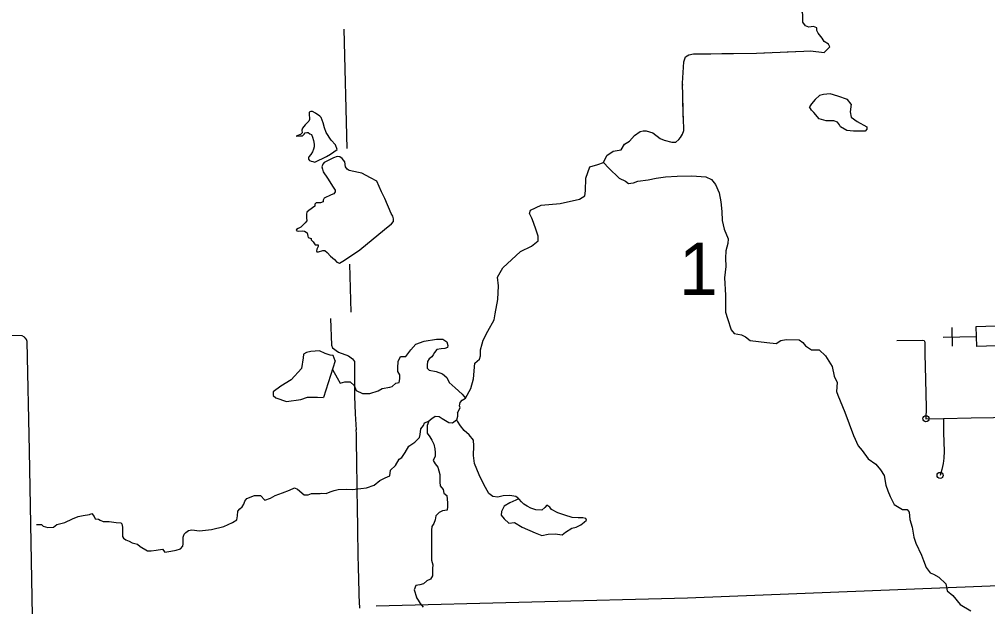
# Model space of a CAD drawing. Extents: x 1367863 to 1368197, y 380048 to 380261.
# Drawn here: x 1368042.42 to 1368072.73, y 380146.25 to 380164.65 of the extents above; entities that cross this region are included whole.
import ezdxf

# ---------------------------------------------------------------- set-up
doc = ezdxf.new("R2010")
doc.units = 0
for name, color, linetype in [('Level 31', 7, 'Continuous'), ('Level 32', 7, 'Continuous'), ('Level 35', 7, 'Continuous'), ('Level 43', 7, 'Continuous'), ('Level 5', 7, 'Continuous'), ('Level 57', 7, 'Continuous')]:
    doc.layers.add(name, color=color, linetype=linetype)

msp = doc.modelspace()

# ---------------------------------------------------------------- linework, layer by layer
at = {"layer": 'Level 31'}
for points in [[(1368069.889, 380154.586), (1368070.694, 380154.598), (1368070.74, 380154.586), (1368070.751, 380154.563), (1368070.763, 380154.511), (1368070.769, 380154.169), (1368070.786, 380153.37), (1368070.803, 380152.478), (1368070.798, 380152.136)], [(1368071.348, 380152.148), (1368072.216, 380152.165), (1368072.916, 380152.177), (1368073.512, 380152.189)], [(1368070.798, 380152.136), (1368071.348, 380152.148)], [(1368071.348, 380152.148), (1368071.353, 380151.691), (1368071.371, 380151.123), (1368071.359, 380150.897), (1368071.342, 380150.729), (1368071.301, 380150.55), (1368071.243, 380150.359)], [(1368053, 380149.528), (1368052.997, 380149.725), (1368052.995, 380149.921), (1368052.992, 380150.113), (1368052.989, 380150.303), (1368052.986, 380150.49), (1368052.984, 380150.676), (1368052.981, 380150.856), (1368052.978, 380151.026), (1368052.973, 380151.181), (1368052.97, 380151.307), (1368052.97, 380151.413), (1368052.969, 380151.502), (1368052.969, 380151.58), (1368052.969, 380151.648), (1368052.967, 380151.708), (1368052.964, 380151.75), (1368052.963, 380151.784), (1368052.961, 380151.792)], [(1368053.078, 380146.203), (1368053.068, 380146.401), (1368053.06, 380146.599), (1368053.054, 380146.798), (1368053.05, 380146.996), (1368053.044, 380147.193), (1368053.037, 380147.387), (1368053.03, 380147.58), (1368053.025, 380147.773), (1368053.022, 380147.966), (1368053.02, 380148.161), (1368053.018, 380148.356), (1368053.017, 380148.551), (1368053.015, 380148.746), (1368053.011, 380148.94), (1368053.007, 380149.135), (1368053.004, 380149.331), (1368053, 380149.528)]]:
    msp.add_lwpolyline(points, dxfattribs=at)
for centre in [(1368070.798, 380152.136), (1368071.243, 380150.359)]:
    msp.add_circle(centre, 0.097, dxfattribs=at)
at = {"layer": 'Level 32'}
for points in [[(1368052.157, 380155.277), (1368052.189, 380154.437), (1368052.222, 380154.361), (1368052.407, 380154.219), (1368052.723, 380154.11), (1368052.843, 380154.012), (1368052.909, 380153.925), (1368052.909, 380153.75), (1368052.909, 380153.26), (1368052.909, 380152.846), (1368052.931, 380152.29), (1368052.961, 380151.792)], [(1368043.011, 380136.212), (1368042.731, 380151.129), (1368042.659, 380154.556), (1368042.643, 380154.618), (1368042.607, 380154.662), (1368042.594, 380154.674), (1368042.578, 380154.694), (1368042.51, 380154.734), (1368041.154, 380154.752)]]:
    msp.add_lwpolyline(points, dxfattribs=at)
at = {"layer": 'Level 35'}
for points in [[(1368067.608, 380163.609), (1368067.786, 380163.788), (1368067.748, 380163.873), (1368067.615, 380163.958), (1368067.546, 380164.06), (1368067.421, 380164.215), (1368067.382, 380164.293), (1368067.382, 380164.378), (1368067.274, 380164.428), (1368067.134, 380164.405), (1368067.033, 380164.443), (1368066.94, 380164.56), (1368066.94, 380164.599), (1368066.947, 380164.677), (1368066.947, 380164.785), (1368066.932, 380164.863), (1368066.87, 380164.948), (1368066.846, 380164.987), (1368066.839, 380165.034), (1368066.753, 380165.151), (1368066.536, 380165.492)], [(1368068.462, 380161.992), (1368068.338, 380162.132), (1368068.043, 380162.241), (1368067.802, 380162.311), (1368067.592, 380162.295), (1368067.468, 380162.257), (1368067.328, 380162.14), (1368067.212, 380162), (1368067.157, 380161.907)], [(1368068.462, 380161.992), (1368068.431, 380161.752), (1368068.462, 380161.588), (1368068.649, 380161.448), (1368068.952, 380161.285), (1368068.952, 380161.208), (1368068.897, 380161.145), (1368068.781, 380161.145), (1368068.532, 380161.145), (1368068.322, 380161.161), (1368068.128, 380161.285), (1368068.089, 380161.347), (1368068.035, 380161.425), (1368067.911, 380161.472), (1368067.678, 380161.464), (1368067.452, 380161.534), (1368067.289, 380161.728), (1368067.212, 380161.806), (1368067.157, 380161.907)], [(1368052.367, 380160.575), (1368052.315, 380160.713), (1368052.183, 380160.865), (1368052.019, 380161.101), (1368051.968, 380161.251), (1368051.93, 380161.406), (1368051.867, 380161.57), (1368051.827, 380161.613), (1368051.686, 380161.705), (1368051.597, 380161.759), (1368051.574, 380161.762), (1368051.539, 380161.762), (1368051.516, 380161.754), (1368051.488, 380161.734), (1368051.488, 380161.702), (1368051.488, 380161.659), (1368051.505, 380161.555), (1368051.505, 380161.506), (1368051.476, 380161.455), (1368051.37, 380161.34), (1368051.281, 380161.236), (1368051.264, 380161.179), (1368051.266, 380161.095), (1368051.215, 380161.041), (1368051.082, 380160.989), (1368051.206, 380160.998), (1368051.278, 380161.003), (1368051.332, 380161.046), (1368051.367, 380161.09), (1368051.422, 380161.098), (1368051.459, 380161.098), (1368051.511, 380161.061), (1368051.56, 380161.035), (1368051.591, 380160.957), (1368051.631, 380160.854), (1368051.643, 380160.733), (1368051.646, 380160.65), (1368051.628, 380160.581), (1368051.594, 380160.5), (1368051.545, 380160.414), (1368051.479, 380160.339), (1368051.465, 380160.305), (1368051.468, 380160.262), (1368051.496, 380160.224), (1368051.548, 380160.204), (1368051.603, 380160.198), (1368051.672, 380160.178)], [(1368056.138, 380152.323), (1368056.222, 380152.473), (1368056.199, 380152.535), (1368056.222, 380152.644), (1368056.284, 380152.714), (1368056.385, 380152.784), (1368056.548, 380153.087), (1368056.634, 380153.39), (1368056.681, 380153.88), (1368056.82, 380154.004), (1368056.851, 380154.105), (1368056.851, 380154.175), (1368056.851, 380154.299), (1368056.906, 380154.478), (1368056.937, 380154.602), (1368057.084, 380154.874), (1368057.286, 380155.232), (1368057.317, 380155.418), (1368057.397, 380155.875), (1368057.413, 380156.294), (1368057.381, 380156.569), (1368057.558, 380156.867), (1368058.106, 380157.375), (1368058.453, 380157.544), (1368058.655, 380157.714), (1368058.655, 380157.851), (1368058.598, 380158.044), (1368058.518, 380158.278), (1368058.461, 380158.415), (1368058.389, 380158.56), (1368058.421, 380158.665), (1368058.754, 380158.821), (1368059.346, 380158.88), (1368059.958, 380159.019), (1368060.116, 380159.117), (1368060.136, 380159.275), (1368060.155, 380159.67), (1368060.274, 380160.025), (1368060.53, 380160.104), (1368060.708, 380160.163), (1368060.807, 380160.38), (1368061.004, 380160.518), (1368061.261, 380160.558), (1368061.359, 380160.736), (1368061.517, 380160.834), (1368061.675, 380161.013), (1368061.854, 380161.138), (1368061.947, 380161.153), (1368062.04, 380161.153), (1368062.25, 380161.091), (1368062.475, 380160.912), (1368062.607, 380160.858), (1368062.848, 380160.796), (1368062.965, 380160.803), (1368063.058, 380160.881), (1368063.112, 380160.951), (1368063.175, 380161.052), (1368063.221, 380161.161), (1368063.221, 380161.231), (1368063.221, 380161.293), (1368063.219, 380161.308)], [(1368053.607, 380159.577), (1368053.407, 380159.687), (1368053.139, 380159.825), (1368053.036, 380159.852), (1368052.74, 380159.914), (1368052.678, 380159.949), (1368052.63, 380160.031), (1368052.602, 380160.183), (1368052.526, 380160.286), (1368052.451, 380160.341), (1368052.368, 380160.348), (1368052.251, 380160.313), (1368051.962, 380160.162), (1368051.914, 380160.107), (1368051.887, 380160.024), (1368051.907, 380159.955), (1368051.928, 380159.866), (1368052.059, 380159.673), (1368052.237, 380159.391), (1368052.299, 380159.301), (1368052.299, 380159.24), (1368052.258, 380159.184), (1368052.182, 380159.15), (1368051.955, 380159.047), (1368051.928, 380158.985), (1368051.928, 380158.93), (1368051.845, 380158.902), (1368051.783, 380158.902), (1368051.708, 380158.902), (1368051.666, 380158.861), (1368051.666, 380158.799), (1368051.481, 380158.661), (1368051.419, 380158.606), (1368051.405, 380158.544), (1368051.405, 380158.434), (1368051.419, 380158.331), (1368051.364, 380158.269), (1368051.226, 380158.138), (1368051.143, 380158.097), (1368051.095, 380158.062), (1368051.088, 380158.028), (1368051.15, 380158.014), (1368051.281, 380158.021), (1368051.343, 380158.014), (1368051.426, 380157.959), (1368051.439, 380157.911), (1368051.446, 380157.856), (1368051.46, 380157.815), (1368051.494, 380157.801), (1368051.549, 380157.787), (1368051.549, 380157.739), (1368051.611, 380157.677), (1368051.68, 380157.587), (1368051.77, 380157.581), (1368051.776, 380157.532), (1368051.735, 380157.443), (1368051.721, 380157.388), (1368051.728, 380157.367), (1368051.783, 380157.367), (1368051.914, 380157.402), (1368051.976, 380157.402), (1368052.052, 380157.34), (1368052.162, 380157.23), (1368052.279, 380157.126), (1368052.361, 380157.037), (1368052.437, 380157.009), (1368052.595, 380157.099)], [(1368051.672, 380160.178), (1368052.031, 380160.354), (1368052.154, 380160.428), (1368052.367, 380160.575)], [(1368060.708, 380160.163), (1368060.875, 380159.988), (1368061.19, 380159.673), (1368061.391, 380159.573), (1368061.491, 380159.501), (1368061.634, 380159.53), (1368061.648, 380159.53), (1368061.777, 380159.573), (1368062.106, 380159.616), (1368062.349, 380159.673), (1368062.65, 380159.716), (1368063.008, 380159.73), (1368063.466, 380159.744), (1368063.909, 380159.716), (1368064.081, 380159.63), (1368064.21, 380159.472), (1368064.324, 380159.215), (1368064.381, 380158.928), (1368064.41, 380158.628), (1368064.424, 380158.342), (1368064.482, 380158.07), (1368064.61, 380157.769), (1368064.596, 380157.626), (1368064.539, 380157.397), (1368064.525, 380157.168), (1368064.539, 380156.91), (1368064.496, 380156.552), (1368064.525, 380156.008), (1368064.525, 380155.479), (1368064.582, 380155.278), (1368064.696, 380154.92), (1368064.796, 380154.806), (1368065.025, 380154.763), (1368065.154, 380154.706), (1368065.297, 380154.591), (1368065.813, 380154.519), (1368066.113, 380154.491), (1368066.256, 380154.591), (1368066.428, 380154.62), (1368066.829, 380154.605), (1368066.943, 380154.519), (1368067.029, 380154.419), (1368067.215, 380154.29), (1368067.458, 380154.29), (1368067.659, 380154.104), (1368067.859, 380153.775), (1368067.93, 380153.474), (1368068.016, 380153.274), (1368068.002, 380152.988), (1368068.045, 380152.873), (1368068.26, 380152.344), (1368068.531, 380151.614), (1368068.675, 380151.284), (1368068.803, 380151.141), (1368068.989, 380150.883), (1368069.233, 380150.712), (1368069.376, 380150.54), (1368069.49, 380150.354), (1368069.547, 380150.053), (1368069.605, 380149.881), (1368069.676, 380149.695), (1368069.805, 380149.452), (1368070.063, 380149.294), (1368070.206, 380149.294), (1368070.277, 380149.209), (1368070.292, 380148.98), (1368070.363, 380148.736), (1368070.42, 380148.421), (1368070.478, 380148.235), (1368070.664, 380147.863), (1368070.721, 380147.691), (1368070.807, 380147.476), (1368070.936, 380147.305), (1368071.036, 380147.262), (1368071.207, 380147.176), (1368071.422, 380146.961), (1368071.465, 380146.746), (1368071.637, 380146.603), (1368071.866, 380146.317), (1368072.209, 380146.117)], [(1368052.595, 380157.099), (1368053.077, 380157.429), (1368053.848, 380158.069), (1368054.068, 380158.241), (1368054.13, 380158.317), (1368054.13, 380158.393), (1368054.109, 380158.482), (1368054.061, 380158.565), (1368053.861, 380159.033), (1368053.758, 380159.246), (1368053.607, 380159.577)], [(1368052.221, 380153.683), (1368052.369, 380153.421), (1368052.463, 380153.25), (1368052.602, 380153.297), (1368052.773, 380153.297), (1368052.898, 380153.18), (1368052.96, 380153.025), (1368053.162, 380152.931), (1368053.387, 380152.931), (1368053.651, 380153.009), (1368053.775, 380153.079), (1368054.016, 380153.126), (1368054.086, 380153.149), (1368054.203, 380153.25), (1368054.304, 380153.273), (1368054.327, 380153.382), (1368054.327, 380153.514), (1368054.265, 380153.615), (1368054.265, 380153.732), (1368054.28, 380153.926), (1368054.35, 380154.082), (1368054.428, 380154.082), (1368054.513, 380154.082), (1368054.676, 380154.299), (1368054.832, 380154.47), (1368055.088, 380154.571), (1368055.476, 380154.626), (1368055.671, 380154.626), (1368055.795, 380154.548), (1368055.826, 380154.431), (1368055.818, 380154.369), (1368055.733, 380154.338), (1368055.624, 380154.33), (1368055.492, 380154.307), (1368055.414, 380154.214), (1368055.368, 380154.136), (1368055.329, 380154.074), (1368055.251, 380154.012), (1368055.197, 380153.934), (1368055.181, 380153.81), (1368055.189, 380153.724), (1368055.251, 380153.654), (1368055.469, 380153.615), (1368055.663, 380153.538), (1368055.803, 380153.429), (1368055.873, 380153.273), (1368056.059, 380153.102), (1368056.277, 380152.908), (1368056.385, 380152.784)], [(1368052.307, 380153.949), (1368052.245, 380154.12), (1368052.144, 380154.128), (1368051.989, 380154.183), (1368051.81, 380154.268), (1368051.546, 380154.245), (1368051.406, 380154.214), (1368051.313, 380154.159), (1368051.305, 380154.043), (1368051.251, 380153.709), (1368050.924, 380153.359), (1368050.598, 380153.157), (1368050.365, 380152.978), (1368050.365, 380152.862), (1368050.451, 380152.792), (1368050.777, 380152.675), (1368051.227, 380152.737), (1368051.437, 380152.815), (1368051.631, 380152.815), (1368051.756, 380152.815), (1368051.934, 380152.799)], [(1368052.307, 380153.949), (1368051.934, 380152.799)], [(1368056.138, 380152.323), (1368056.131, 380152.206), (1368056.099, 380152.09), (1368055.975, 380151.997), (1368055.859, 380152.012), (1368055.758, 380152.074), (1368055.657, 380152.137), (1368055.556, 380152.199), (1368055.439, 380152.206), (1368055.33, 380152.129), (1368055.237, 380152.059), (1368055.183, 380151.919), (1368055.183, 380151.802), (1368055.183, 380151.686), (1368055.268, 380151.569), (1368055.33, 380151.468), (1368055.393, 380151.336), (1368055.424, 380151.196), (1368055.439, 380151.08), (1368055.439, 380150.963), (1368055.369, 380150.831), (1368055.431, 380150.722), (1368055.517, 380150.621), (1368055.548, 380150.505), (1368055.579, 380150.388), (1368055.579, 380150.264), (1368055.579, 380150.147), (1368055.595, 380150.031), (1368055.688, 380149.922), (1368055.703, 380149.805), (1368055.797, 380149.735), (1368055.812, 380149.619), (1368055.82, 380149.502), (1368055.82, 380149.386), (1368055.812, 380149.269), (1368055.664, 380149.246), (1368055.556, 380149.199), (1368055.455, 380149.09), (1368055.431, 380148.974), (1368055.393, 380148.857), (1368055.33, 380148.756), (1368055.315, 380148.64), (1368055.315, 380148.523), (1368055.315, 380148.406), (1368055.315, 380148.29), (1368055.315, 380148.173), (1368055.315, 380148.057), (1368055.315, 380147.94), (1368055.315, 380147.824), (1368055.315, 380147.707), (1368055.362, 380147.559), (1368055.354, 380147.443), (1368055.354, 380147.326), (1368055.346, 380147.21), (1368055.284, 380147.109), (1368055.175, 380147.062), (1368055.066, 380146.961), (1368054.95, 380146.93), (1368054.833, 380146.914), (1368054.779, 380146.775), (1368054.847, 380146.548)], [(1368047.819, 380148.655), (1368048.052, 380148.624), (1368048.432, 380148.671), (1368048.821, 380148.756), (1368049.085, 380148.888), (1368049.225, 380148.974), (1368049.248, 380149.098), (1368049.256, 380149.238), (1368049.318, 380149.316), (1368049.388, 380149.378), (1368049.45, 380149.463), (1368049.473, 380149.557), (1368049.543, 380149.642), (1368049.784, 380149.735), (1368049.807, 380149.735), (1368049.971, 380149.728), (1368050.103, 380149.58), (1368050.281, 380149.65), (1368050.429, 380149.728), (1368050.654, 380149.813), (1368050.872, 380149.899), (1368051.035, 380149.968), (1368051.128, 380149.93), (1368051.33, 380149.751), (1368051.454, 380149.751), (1368051.563, 380149.79), (1368051.672, 380149.797), (1368051.765, 380149.797), (1368051.835, 380149.797), (1368051.889, 380149.805), (1368052.021, 380149.797), (1368052.146, 380149.844), (1368052.27, 380149.883), (1368052.402, 380149.922), (1368052.65, 380149.93), (1368052.837, 380149.914), (1368053.109, 380149.953), (1368053.28, 380149.968), (1368053.521, 380150.054), (1368053.707, 380150.202), (1368053.87, 380150.287), (1368054.018, 380150.349), (1368054.041, 380150.528), (1368054.189, 380150.676), (1368054.305, 380150.87), (1368054.391, 380150.924), (1368054.499, 380151.08), (1368054.608, 380151.274), (1368054.794, 380151.398), (1368054.942, 380151.546), (1368054.965, 380151.639), (1368054.989, 380151.818), (1368055.066, 380151.919), (1368055.097, 380152.012), (1368055.237, 380152.059)], [(1368058.049, 380149.627), (1368057.956, 380149.704), (1368057.77, 380149.735), (1368057.56, 380149.72), (1368057.397, 380149.681), (1368057.241, 380149.704), (1368057.117, 380149.797), (1368056.962, 380150.077), (1368056.814, 380150.38), (1368056.667, 380150.73), (1368056.635, 380150.986), (1368056.643, 380151.282), (1368056.635, 380151.468), (1368056.503, 380151.631), (1368056.34, 380151.764), (1368056.224, 380151.911), (1368056.138, 380152.059), (1368056.099, 380152.09)], [(1368058.049, 380149.627), (1368057.77, 380149.502), (1368057.591, 380149.401), (1368057.513, 380149.23), (1368057.498, 380149.114), (1368057.591, 380148.997), (1368057.739, 380148.865), (1368057.917, 380148.881), (1368058.158, 380148.741), (1368058.562, 380148.562), (1368058.779, 380148.476), (1368058.974, 380148.523), (1368059.191, 380148.531), (1368059.409, 380148.5), (1368059.51, 380148.585), (1368059.712, 380148.71), (1368059.851, 380148.741), (1368059.991, 380148.811), (1368060.1, 380148.896), (1368060.17, 380148.958), (1368060.154, 380149.013), (1368060.061, 380149.028), (1368059.914, 380149.028), (1368059.719, 380149.044), (1368059.494, 380149.114), (1368059.277, 380149.191), (1368059.075, 380149.292), (1368059.028, 380149.362), (1368058.935, 380149.424), (1368058.873, 380149.355), (1368058.772, 380149.269), (1368058.585, 380149.285), (1368058.43, 380149.331), (1368058.313, 380149.393), (1368058.212, 380149.463), (1368058.135, 380149.533), (1368058.065, 380149.619)], [(1368042.959, 380148.827), (1368043.107, 380148.827), (1368043.166, 380148.768), (1368043.313, 380148.724), (1368043.49, 380148.738), (1368043.593, 380148.827), (1368043.844, 380148.886), (1368044.08, 380149.004), (1368044.257, 380149.078), (1368044.419, 380149.107), (1368044.611, 380149.137), (1368044.685, 380149.166), (1368044.758, 380149.078), (1368044.788, 380149.004), (1368044.891, 380148.989), (1368044.95, 380148.96), (1368045.039, 380148.915), (1368045.112, 380148.915), (1368045.23, 380148.915), (1368045.451, 380148.886), (1368045.599, 380148.871), (1368045.628, 380148.842), (1368045.643, 380148.738), (1368045.643, 380148.664), (1368045.643, 380148.546), (1368045.643, 380148.443), (1368045.673, 380148.399), (1368045.746, 380148.34), (1368045.85, 380148.296), (1368045.953, 380148.251), (1368046.115, 380148.207), (1368046.204, 380148.133), (1368046.425, 380148.001), (1368046.543, 380148.001), (1368046.705, 380148.015), (1368046.897, 380148.045), (1368046.971, 380147.956), (1368047.162, 380147.986), (1368047.325, 380148.015), (1368047.457, 380148.06), (1368047.531, 380148.148), (1368047.546, 380148.222), (1368047.546, 380148.34), (1368047.546, 380148.428), (1368047.575, 380148.517), (1368047.634, 380148.576), (1368047.708, 380148.635), (1368047.819, 380148.655)], [(1368055.073, 380146.229), (1368054.979, 380146.353), (1368054.917, 380146.454), (1368054.847, 380146.548)]]:
    msp.add_lwpolyline(points, dxfattribs=at)
at = {"layer": 'Level 43'}
for points in [[(1368063.219, 380161.309), (1368063.206, 380161.417), (1368063.182, 380162.653), (1368063.221, 380163.313), (1368063.268, 380163.469), (1368063.376, 380163.539), (1368063.524, 380163.57), (1368064.06, 380163.57), (1368065.497, 380163.593), (1368066.973, 380163.655), (1368067.188, 380163.663), (1368067.608, 380163.609)], [(1368063.183, 380162.589), (1368063.182, 380162.653), (1368063.221, 380163.313), (1368063.268, 380163.469), (1368063.376, 380163.539), (1368063.524, 380163.57), (1368063.893, 380163.57)], [(1368064.405, 380163.576), (1368065.497, 380163.593), (1368065.941, 380163.612)], [(1368066.453, 380163.634), (1368066.973, 380163.655), (1368067.188, 380163.663), (1368067.608, 380163.609)], [(1368063.219, 380161.309), (1368063.206, 380161.417), (1368063.193, 380162.077)]]:
    msp.add_lwpolyline(points, dxfattribs=at)
at = {"layer": 'Level 5'}
for points in [[(1368052.572, 380164.337), (1368052.666, 380160.604)], [(1368052.757, 380156.983), (1368052.795, 380155.473)], [(1368073.601, 380146.926), (1368063.333, 380146.512), (1368053.586, 380146.261)]]:
    msp.add_lwpolyline(points, dxfattribs=at)
at = {"layer": 'Level 57'}
for p, q in [((1368071.634, 380154.408), (1368071.62, 380154.99)), ((1368071.336, 380154.692), (1368072.381, 380154.717))]:
    msp.add_line(p, q, dxfattribs=at)
msp.add_lwpolyline([(1368072.994, 380154.417), (1368072.388, 380154.402), (1368072.373, 380155.03), (1368072.978, 380155.045)], close=True, dxfattribs=at)

# ---------------------------------------------------------------- texts
at = {"layer": 'Level 5'}
msp.add_text('1', height=1.639, dxfattribs=at).set_placement((1368063.067, 380156.013))

doc.saveas('drawing.dxf')
